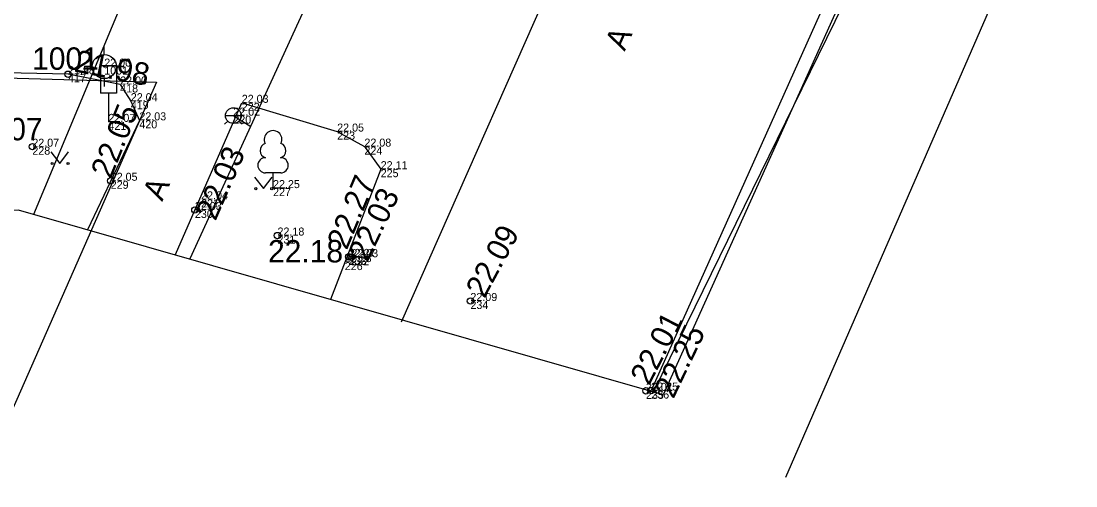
# Model space of a CAD drawing. Extents: x 714279 to 714471, y 6589851 to 6590083.
# Drawn here: x 714372.9 to 714405.84, y 6589958.28 to 6589972.81 of the extents above; entities that cross this region are included whole.
import ezdxf

# ---------------------------------------------------------------- set-up
doc = ezdxf.new("R2010")
doc.units = 0
for name, color, linetype in [('ALUSVORK', 7, 'Continuous'), ('HALJASTUS', 7, 'Continuous'), ('KORGUS', 7, 'Continuous'), ('KPKAABEL', 7, 'Continuous'), ('LIIKLUS', 7, 'Continuous'), ('MOOTKORG', 7, 'Continuous'), ('MOOTMPUNKT', 7, 'Continuous'), ('MOOTPIIR', 7, 'Continuous'), ('PIIR', 7, 'Continuous'), ('PUU', 7, 'Continuous'), ('SITRASS', 7, 'Continuous'), ('SKTRASS', 7, 'Continuous'), ('TEE', 7, 'Continuous'), ('VKAEV', 7, 'Continuous'), ('VTRASS', 7, 'Continuous')]:
    doc.layers.add(name, color=color, linetype=linetype)

# ---------------------------------------------------------------- blocks, each defined once
blk = doc.blocks.new('VESIIB')
at = {"layer": 'VKAEV'}
for p, q in [((-0.7, 0), (0.7, 0)), ((-0.495, -0.495), (-0.774, -0.774)), ((0.495, -0.495), (0.774, -0.774))]:
    blk.add_line(p, q, dxfattribs=at)
blk.add_circle((0, 0), 0.7, dxfattribs=at)
blk = doc.blocks.new('LEHTP1')
at = {"layer": 'PUU'}
for p, q in [((0.48, 0.95), (-0.48, 0.95)), ((0, 0), (0, 0.95)), ((0.76, 0), (0, 0))]:
    blk.add_line(p, q, dxfattribs=at)
for centre, radius, start, end in [((0, 3.04), 0.554, 332.5799, 207.4201), ((-0.34, 2.345), 0.465, 109.02174, 253.14154), ((0.34, 2.345), 0.465, 286.85082, 70.98591), ((-0.475, 1.425), 0.475, 90.0016, 269.3953), ((0.475, 1.425), 0.475, 270.6047, 89.9984)]:
    blk.add_arc(centre, radius, start, end, dxfattribs=at)
blk = doc.blocks.new('RING02')
at = {"layer": 'KORGUS'}
blk.add_circle((0, 0), 0.2, dxfattribs=at)
blk = doc.blocks.new('RING02_1')
at = {"layer": 'KORGUS'}
blk.add_circle((0, 0), 0.2, dxfattribs=at)
blk = doc.blocks.new('RING02_2')
at = {"layer": 'KORGUS'}
blk.add_circle((0, 0), 0.2, dxfattribs=at)
blk = doc.blocks.new('SPYMAR')
at = {"layer": 'ALUSVORK'}
for p, q in [((0, 0.75), (0, 1.25)), ((-0.75, 0), (-1.25, 0)), ((0.75, 0), (1.25, 0)), ((0, -0.75), (0, -1.25))]:
    blk.add_line(p, q, dxfattribs=at)
for radius in [0.75, 0.044]:
    blk.add_circle((0, 0), radius, dxfattribs=at)
blk = doc.blocks.new('LIIKLM')
at = {"layer": 'LIIKLUS'}
for p, q in [((-0.5, 3.5), (-0.5, 1.8)), ((0.5, 3.5), (-0.5, 3.5)), ((0.5, 3.5), (0.5, 1.8)), ((0.5, 1.8), (-0.5, 1.8)), ((0, 1.8), (0, 0)), ((0.5, 0), (0, 0))]:
    blk.add_line(p, q, dxfattribs=at)
blk = doc.blocks.new('MURU_1')
at = {"layer": 'HALJASTUS'}
for p, q in [((-0.93, 1.21), (0, 0)), ((0, 0), (0.89, 1.21))]:
    blk.add_line(p, q, dxfattribs=at)
for centre in [(-0.8, 0), (0.86, 0)]:
    blk.add_circle(centre, 0.11, dxfattribs=at)

msp = doc.modelspace()

# ---------------------------------------------------------------- linework, layer by layer
at = {"layer": 'KPKAABEL'}
msp.add_lwpolyline([(714396.776, 6589958.555), (714410.513, 6589990.138), (714421.117, 6590017.14), (714434.01, 6590042.696)], dxfattribs=at)
at = {"layer": 'MOOTPIIR'}
msp.add_lwpolyline([(714325.392, 6590064.148), (714418.405, 6590047.495), (714428.059, 6590039.059), (714392.952, 6589961.13), (714372.822, 6589966.903), (714302.696, 6589965.199), (714319.941, 6590042.637), (714325.392, 6590064.148)], dxfattribs=at)
at = {"layer": 'PIIR'}
msp.add_lwpolyline([(714305.517, 6589967.896), (714327.878, 6589970.35), (714360.817, 6589971.365), (714377.13, 6589970.9), (714368.352, 6589950.974)], dxfattribs=at)
at = {"layer": 'SITRASS'}
msp.add_lwpolyline([(714403.003, 6590037.966), (714373.288, 6589966.766)], dxfattribs=at)
at = {"layer": 'SKTRASS'}
msp.add_lwpolyline([(714392.66, 6589961.24), (714403.716, 6589983.842)], dxfattribs=at)
at = {"layer": 'TEE'}
for points in [[(714428.059, 6590039.059), (714427.912, 6590038.899), (714421.383, 6590024.973), (714411.21, 6590002.295), (714399.51, 6589976.749), (714392.577, 6589961.261), (714392.577, 6589961.261)], [(714375.994, 6589970.826), (714374.365, 6589971.147), (714359.209, 6589971.476), (714342.555, 6589971.127)], [(714375.994, 6589970.826), (714376.325, 6589970.304), (714376.593, 6589969.705), (714376.593, 6589969.705)], [(714377.717, 6589965.509), (714379.79, 6589970.253), (714382.77, 6589969.354), (714383.621, 6589968.885), (714384.128, 6589968.179), (714382.557, 6589964.11)], [(714376.593, 6589969.705), (714374.973, 6589966.284)]]:
    msp.add_lwpolyline(points, dxfattribs=at)
at = {"layer": 'VTRASS'}
for points in [[(714378.183, 6589965.384), (714401.816, 6590016.993), (714414.734, 6590044.36), (714416.367, 6590047.881)], [(714384.776, 6589963.41), (714420.935, 6590045.157)], [(714380.069, 6589969.501), (714379.507, 6589969.854)]]:
    msp.add_lwpolyline(points, dxfattribs=at)

# ---------------------------------------------------------------- block references
at = {"layer": 'ALUSVORK', "xscale": 0.5, "yscale": 0.5}
msp.add_blockref('SPYMAR', (714375.497, 6589971.385), dxfattribs=at)
at = {"layer": 'HALJASTUS', "xscale": 0.3, "yscale": 0.3}
for p in [(714374.109, 6589968.354), (714380.468, 6589967.57)]:
    msp.add_blockref('MURU_1', p, dxfattribs=at)
at = {"layer": 'KORGUS', "xscale": 0.5, "yscale": 0.5}
for name, p in [('RING02_2', (714374.365, 6589971.147)), ('RING02', (714373.251, 6589968.881)), ('RING02_1', (714375.698, 6589967.817)), ('RING02_1', (714378.327, 6589966.904)), ('RING02', (714380.907, 6589966.105)), ('RING02_1', (714383.13, 6589965.438)), ('RING02_2', (714383.211, 6589965.427)), ('RING02_1', (714386.93, 6589964.059)), ('RING02_2', (714392.411, 6589961.252)), ('RING02_1', (714392.577, 6589961.261))]:
    msp.add_blockref(name, p, dxfattribs=at)
at = {"layer": 'LIIKLUS', "xscale": 0.5, "yscale": 0.5}
msp.add_blockref('LIIKLM', (714375.628, 6589969.657), dxfattribs=at)
at = {"layer": 'PUU', "xscale": 0.5, "yscale": 0.5}
msp.add_blockref('LEHTP1', (714380.767, 6589967.588), dxfattribs=at)
at = {"layer": 'VKAEV', "xscale": 0.35, "yscale": 0.35}
msp.add_blockref('VESIIB', (714379.527, 6589969.852), dxfattribs=at)

# ---------------------------------------------------------------- texts
at = {"layer": 'ALUSVORK'}
msp.add_text('1001', height=0.7, dxfattribs=at).set_placement((714373.244, 6589971.285))
at = {"layer": 'KORGUS'}
for s, rotation, p in [('21.98', 348.6858, (714374.531, 6589971.235)), ('22.05', 67.9513, (714375.701, 6589967.851)), ('22.03', 66.3207, (714378.969, 6589966.539)), ('22.27', 67.1174, (714383.07, 6589965.629)), ('22.03', 64.4263, (714383.718, 6589965.255)), ('22.09', 61.626, (714387.364, 6589964.118)), ('22.01', 62.589, (714392.507, 6589961.392)), ('22.25', 64.3932, (714393.268, 6589960.978))]:
    msp.add_text(s, height=0.7, rotation=rotation, dxfattribs=at).set_placement(p)
for s, p in [('22.07', (714371.229, 6589969.081)), ('22.18', (714380.611, 6589965.265))]:
    msp.add_text(s, height=0.7, dxfattribs=at).set_placement(p)
at = {"layer": 'MOOTKORG'}
for s, p in [('22.00', (714375.497, 6589971.385)), ('21.98', (714374.365, 6589971.147)), ('22.00', (714375.994, 6589970.826)), ('22.04', (714376.325, 6589970.304)), ('22.03', (714379.79, 6589970.253)), ('22.07', (714375.628, 6589969.657)), ('22.03', (714376.593, 6589969.705)), ('22.02', (714379.527, 6589969.852)), ('22.05', (714382.77, 6589969.354)), ('22.07', (714373.251, 6589968.881)), ('22.08', (714383.621, 6589968.885)), ('22.11', (714384.128, 6589968.179)), ('22.05', (714375.698, 6589967.817)), ('22.25', (714380.767, 6589967.588)), ('22.04', (714378.522, 6589967.235)), ('22.03', (714378.327, 6589966.904)), ('22.18', (714380.907, 6589966.105)), ('22.27', (714383.13, 6589965.438)), ('22.03', (714383.211, 6589965.427)), ('22.28', (714383.007, 6589965.275)), ('22.09', (714386.93, 6589964.059)), ('22.01', (714392.411, 6589961.252)), ('22.25', (714392.577, 6589961.261))]:
    msp.add_text(s, height=0.25, dxfattribs=at).set_placement(p)
at = {"layer": 'MOOTMPUNKT'}
for s, p in [('1001', (714375.497, 6589971.135)), ('417', (714374.365, 6589970.897)), ('418', (714375.994, 6589970.576)), ('419', (714376.325, 6589970.054)), ('222', (714379.79, 6589970.003)), ('421', (714375.628, 6589969.407)), ('420', (714376.593, 6589969.455)), ('220', (714379.527, 6589969.602)), ('223', (714382.77, 6589969.104)), ('228', (714373.251, 6589968.631)), ('224', (714383.621, 6589968.635)), ('225', (714384.128, 6589967.929)), ('229', (714375.698, 6589967.567)), ('227', (714380.767, 6589967.338)), ('221', (714378.522, 6589966.985)), ('230', (714378.327, 6589966.654)), ('231', (714380.907, 6589965.855)), ('233', (714383.13, 6589965.188)), ('232', (714383.211, 6589965.177)), ('226', (714383.007, 6589965.025)), ('234', (714386.93, 6589963.809)), ('235', (714392.411, 6589961.002)), ('236', (714392.577, 6589961.011))]:
    msp.add_text(s, height=0.25, dxfattribs=at).set_placement(p)
at = {"layer": 'TEE'}
for rotation, p in [(66.0638, (714391.745, 6589971.845)), (66.133, (714377.307, 6589967.152))]:
    msp.add_text('A', height=0.7, rotation=rotation, dxfattribs=at).set_placement(p)

doc.saveas('drawing.dxf')
